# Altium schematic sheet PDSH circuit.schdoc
size 250 x 152 mm
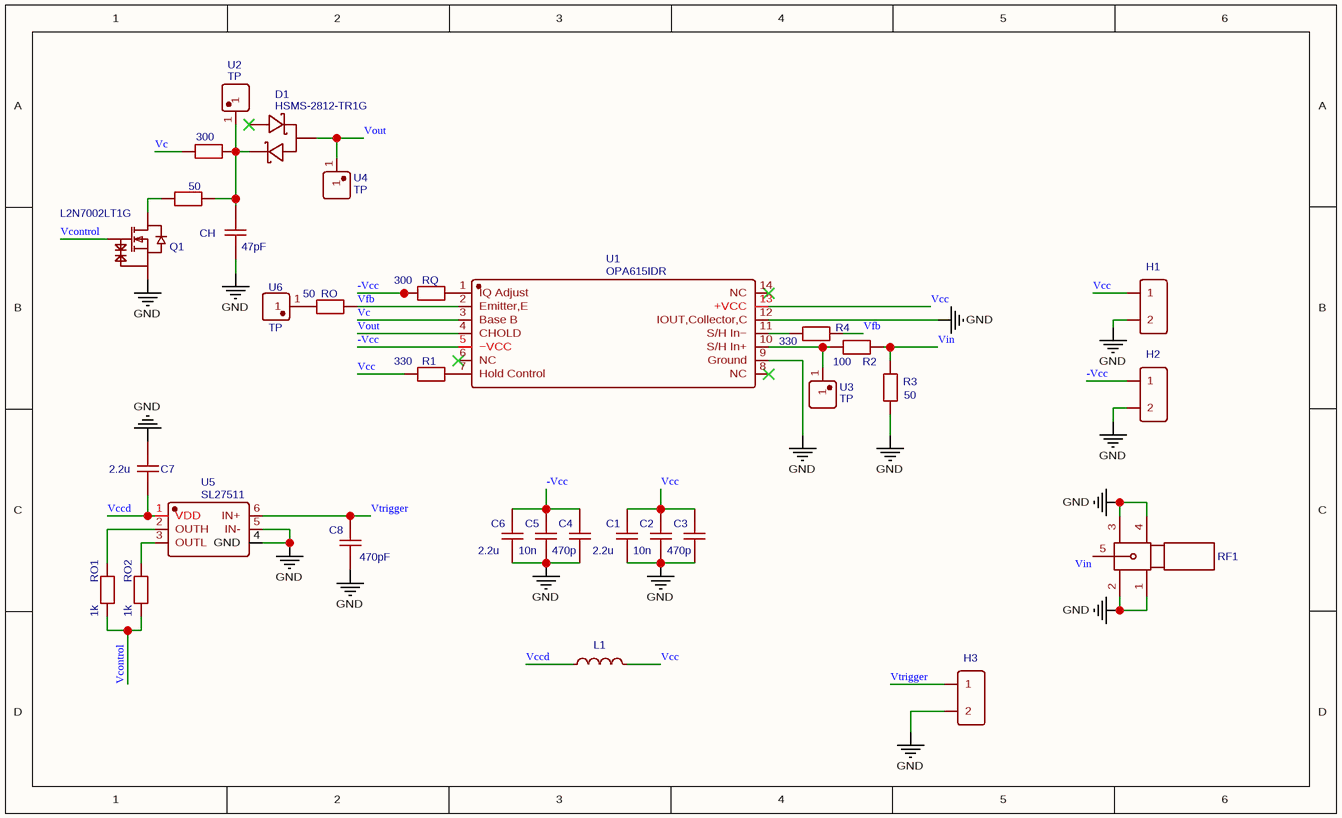
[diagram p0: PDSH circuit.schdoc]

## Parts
C1  2.2u  [C0805]
C2  10n  [C0805]
C3  470p  [C0805]
C4  470p  [C0805]
C5  10n  [C0805]
C6  2.2u  [C0805]
C7  2.2u  [C0805]
C8  470pF  [C0805]
CH  47pF  [C0603]
D1  HSMS-2812-TR1G  [SOT-23-3_L2.9-W1.3-P1.90-LS2.4-BR]
H1  Header-Male-2.54_1x2  [HDR-TH_2P-P2.54-V-M-1]  (value not drawn)
H2  Header-Male-2.54_1x2  [HDR-TH_2P-P2.54-V-M-1]  (value not drawn)
H3  Header-Male-2.54_1x2  [HDR-TH_2P-P2.54-V-M-1]  (value not drawn)
L1  UPZ1608U220-6R0TF  [L0603]  (value not drawn)
Q1  L2N7002LT1G  [SOT-23_L2.9-W1.3-P1.90-LS2.4-BR]
R1  330  [R0603]
R2  100  [R0603]
R3  50  [R0603]
R4  330  [R0603]
RF1  KH-SMA-KE-Z  [SMA-TH_KH-SMA-KE-Z]  (value not drawn)
RO  50  [R0603]
RO1  1k  [R0603]
RO2  1k  [R0603]
RQ  300  [R0603]
RQ1  300  [R0603]
RQ2  50  [R0603]
U1  OPA615IDR  [SOIC-14_L8.7-W3.9-P1.27-LS6.0-BL]
U2  TP  [TESTPOINT-TH_BD3.2]
U3  TP  [TESTPOINT-TH_BD3.2]
U4  TP  [TESTPOINT-TH_BD3.2]
U5  SL27511  [SOT-23-6_L2.9-W1.6-P0.95-LS2.8-BR]
U6  TP  [TESTPOINT-TH_BD3.2]

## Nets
GND: C1.1 C2.1 C3.1 C4.1 C5.1 C6.1 C7.2 C8.1 CH.1 H1.2 H2.2 H3.2 Q1.2(S) R3.1 RF1.1 RF1.2 RF1.3 RF1.4 U1.9(Ground) U1.12(IOUT,Collector,C) U5.4(GND) U5.5(IN-)
-Vcc: C4.2 C5.2 C6.2 H2.1 RQ.1 U1.5(−VCC)
Vc: RQ1.2 U1.3(Base_B)
Vcc: C1.2 C2.2 C3.2 H1.1 L1.2 R1.1 U1.13(+VCC)
Vccd: C7.1 L1.1 U5.1(VDD)
Vcontrol: Q1.1(G) RO1.1 RO2.1
Vfb: R4.2 RO.2 U1.2(Emitter,E)
Vin: R2.2 R3.2 RF1.5
Vout: D1.3 U1.4(CHOLD) U4.1
Vtrigger: C8.2 H3.1 U5.6(IN+)
NetCH_2: CH.2 D1.2 RQ1.1 RQ2.1 U2.1
NetQ1_3: Q1.3(D) RQ2.2
NetR1_2: R1.2 U1.7(Hold_Control)
NetR2_1: R2.1 U1.10(S/H_In+) U3.1
NetR4_1: R4.1 U1.11(S/H_In−)
NetRO1_2: RO1.2 U5.2(OUTH)
NetRO2_2: RO2.2 U5.3(OUTL)
NetRO_1: RO.1 U6.1
NetRQ_2: RQ.2 U1.1(IQ_Adjust)

Not connected (* = marked no-connect by the designer): D1 1*; U1 6(NC)* 8(NC)* 14(NC)*

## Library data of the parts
C1 C6 C7 = 2.2u: Manufacturer: CCTC; Manufacturer Part: TCC0805COG220J251FT; nameAlias: Capacitance; Contributor: LCSC
C2 C5 = 10n: Manufacturer: CCTC; Manufacturer Part: TCC0805COG220J251FT; nameAlias: Capacitance; Contributor: LCSC
C3 C4 = 470p: Manufacturer: CCTC; Manufacturer Part: TCC0805COG220J251FT; nameAlias: Capacitance; Contributor: LCSC
C8 = 470pF: Manufacturer: CCTC; Manufacturer Part: TCC0805COG220J251FT; nameAlias: Capacitance; Contributor: LCSC
CH = 47pF: nameAlias: Value(F); Contributor: LCEDA_Lib
D1 = HSMS-2812-TR1G: Manufacturer: Broadcom; Contributor: LCSC
H1-H3 = Header-Male-2.54_1x2: Manufacturer: TE Connectivity; Manufacturer Part: 826629-2
L1 = UPZ1608U220-6R0TF: Manufacturer: Sunlord; nameAlias: Value(H); Value: 22Ω
Q1 = L2N7002LT1G: Manufacturer: LRC
R1 R4 = 330: nameAlias: Value(Ω); Contributor: LCEDA_Lib
R2 = 100: nameAlias: Value(Ω); Contributor: LCEDA_Lib
R3 RO RQ2 = 50: nameAlias: Value(Ω); Contributor: LCEDA_Lib
RF1 = KH-SMA-KE-Z: Manufacturer: Shenzhen Kinghelm Elec; Contributor: LCSC
RO1 RO2 = 1k: nameAlias: Value(Ω); Contributor: LCEDA_Lib
RQ RQ1 = 300: nameAlias: Value(Ω); Contributor: LCEDA_Lib
U1 = OPA615IDR: Manufacturer: TI(德州仪器); Contributor: LCSC
U2-U4 U6 = TP: Manufacturer: null; Manufacturer Part: TP-橘色测试点; Contributor: LCSC
U5 = SL27511: Manufacturer: Slkor(SLKORMICRO Elec.); Contributor: LCSC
